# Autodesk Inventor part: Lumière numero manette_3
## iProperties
Created: 2010-07
Part Number: Lumière numero manette_3
Document SubType Name: Modeling
Designer: eric
Density: 1 g/cm^3
Author: eric
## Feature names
1. Base1
